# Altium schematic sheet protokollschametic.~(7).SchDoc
size A4; PageSetup: Record=PageOptions|CenterHorizontal=True|CenterVertical=True|PrintScale=0.87|XCorrection=1.00|YCorrection=1.00|PrintKind=2|BorderSize=5000000|LeftOffset=0|BottomOffset=0|Orientation=2|PaperLength=1000|PaperWidth=1000|Scale=100|PaperSource=7|PrintQuality=-4|MediaType=1|DitherType=10|PaperKind=Letter|PrintScaleMode=1
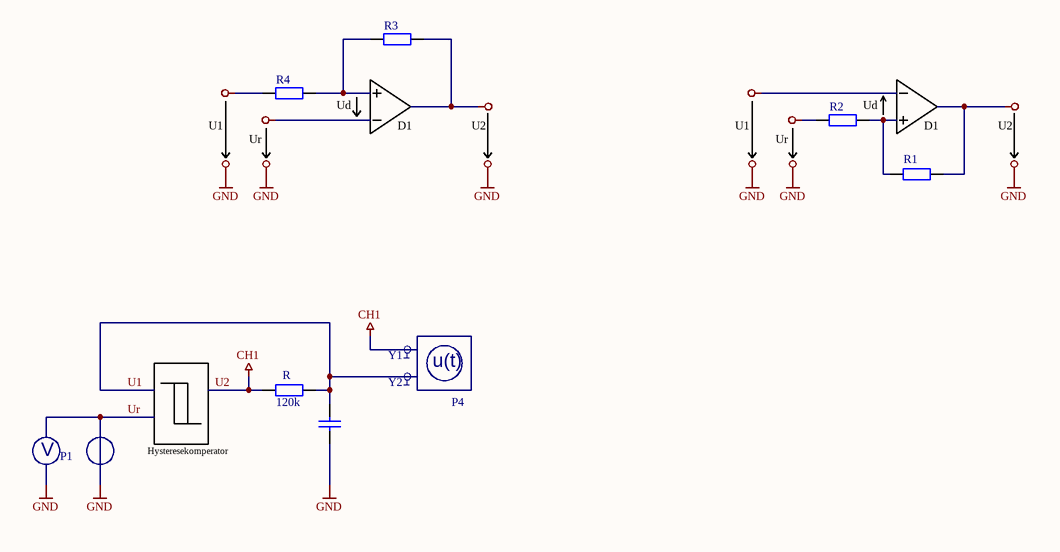
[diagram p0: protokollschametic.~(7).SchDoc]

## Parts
C?  Cap  [RAD-0.3]  (value not drawn)
G?  Spannungsquelle  (value not drawn)
P1  Voltmeter1  (value not drawn)
P4  Oszilloskop2Kanal  (value not drawn)
R  value 120k  [AXIAL-0.4]  (hidden comment: Res2)
R1  Res2  [AXIAL-0.4]  (value not drawn)
R2  Res2  [AXIAL-0.4]  (value not drawn)
R3  Res2  [AXIAL-0.4]  (value not drawn)
R4  Res2  [AXIAL-0.4]  (value not drawn)

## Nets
GND: C?.1 G?.2 P1.2 R1.2 R2.1 R3.2 R4.1
U2: P4.1 R.1  [also labelled CH1]
U1: C?.2 P4.2 R.2
Ur: G?.1 P1.1
NetR1_1: R1.1 R2.2
NetR3_1: R3.1 R4.2

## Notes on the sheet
- (near R4) Ud
- (near R2) Ud
- U1
- (near R4) Ur
- D1
- U2
- (near R2) Ur
- (near R1) D1
- Hysteresekomperator

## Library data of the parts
C? = Cap: Capacitor; Value: 100pF
R = Res2: Resistor
R1-R4 = Res2: Resistor; Value: 1K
